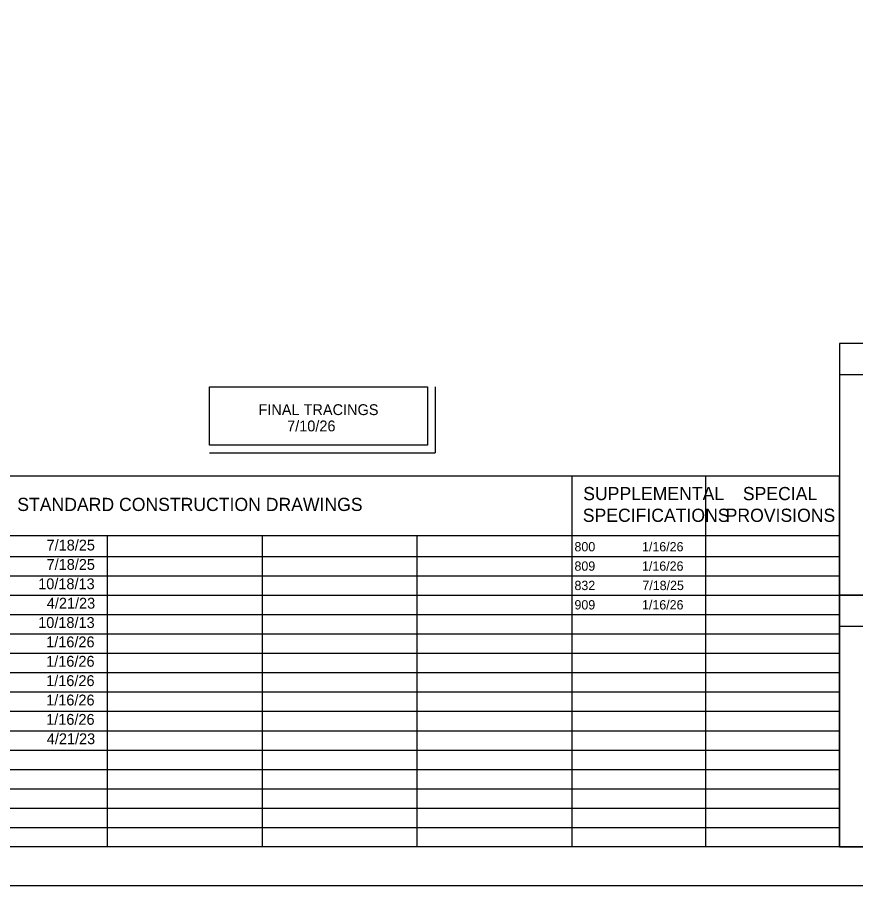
# Model space of a CAD drawing. Extents: x 0 to 34, y 0 to 22.
# Drawn here: x 12.99 to 23.81, y 0 to 11.21 of the extents above; entities that cross this region are included whole.
import ezdxf

# ---------------------------------------------------------------- set-up
doc = ezdxf.new("R2010")
doc.units = 0
for name, color, linetype in [('SH_Border', 7, 'Continuous'), ('SH_Cut_Line', 7, 'Continuous'), ('SH_Data', 7, 'Continuous'), ('SH_Text', 7, 'Continuous')]:
    doc.layers.add(name, color=color, linetype=linetype)

msp = doc.modelspace()

# ---------------------------------------------------------------- linework, layer by layer
at = {"layer": 'SH_Border'}
msp.add_lwpolyline([(1.5, 21.5), (33.5, 21.5), (33.5, 0.5), (1.5, 0.5)], close=True, dxfattribs=at)
at = {"layer": 'SH_Cut_Line'}
msp.add_lwpolyline([(0, 0), (34, 0), (34, 22), (0, 22)], close=True, dxfattribs=at)
at = {"layer": 'SH_Data'}
for p, q in [((23.6, 6.6), (26.4, 6.6)), ((10.15, 5.292), (23.6, 5.292)), ((20.15, 0.5), (20.15, 5.292)), ((21.875, 0.5), (21.875, 5.292)), ((23.6, 0.5), (23.6, 5.292)), ((10.15, 4.521), (23.6, 4.521)), ((14.15, 0.5), (14.15, 4.521)), ((16.15, 0.5), (16.15, 4.521)), ((18.15, 0.5), (18.15, 4.521)), ((10.15, 4.25), (23.6, 4.25)), ((10.15, 4), (23.6, 4)), ((10.15, 3.75), (23.6, 3.75)), ((10.15, 3.5), (23.6, 3.5)), ((23.6, 3.35), (26.4, 3.35)), ((10.15, 3.25), (23.6, 3.25)), ((10.15, 3), (23.6, 3)), ((10.15, 2.75), (23.6, 2.75)), ((10.15, 2.5), (23.6, 2.5)), ((10.15, 2.25), (23.6, 2.25)), ((10.15, 2), (23.6, 2)), ((10.15, 1.75), (23.6, 1.75)), ((10.15, 1.5), (23.6, 1.5)), ((10.15, 1.25), (23.6, 1.25)), ((10.15, 1), (23.6, 1)), ((10.15, 0.75), (23.6, 0.75))]:
    msp.add_line(p, q, dxfattribs=at)
for points in [[(26.4, 7), (23.6, 7), (23.6, 3.75), (26.4, 3.75)], [(26.4, 3.75), (23.6, 3.75), (23.6, 0.5), (26.4, 0.5)]]:
    msp.add_lwpolyline(points, close=True, dxfattribs=at)
at = {"layer": 'SH_Text'}
for p in [(18.381, 6.437), (15.469, 5.587)]:
    msp.add_line(p, (18.381, 5.587), dxfattribs=at)
msp.add_lwpolyline([(15.469, 6.437), (18.281, 6.437), (18.281, 5.687), (15.469, 5.687)], close=True, dxfattribs=at)

# ---------------------------------------------------------------- texts
for s, height, p in [('FINAL TRACINGS', 0.14, (16.1, 6.074)), ('7/10/26', 0.14, (16.47, 5.864)), ('SUPPLEMENTAL', 0.17, (20.293, 4.976)), ('SPECIAL', 0.17, (22.354, 4.976)), ('STANDARD CONSTRUCTION DRAWINGS', 0.17, (12.986, 4.836)), ('SPECIFICATIONS', 0.17, (20.287, 4.696)), ('PROVISIONS', 0.17, (22.132, 4.696)), ('7/18/25', 0.14, (13.364, 4.326)), ('800', 0.12, (20.18, 4.315)), ('1/16/26', 0.12, (21.052, 4.315)), ('7/18/25', 0.14, (13.364, 4.076)), ('809', 0.12, (20.18, 4.065)), ('1/16/26', 0.12, (21.052, 4.065)), ('10/18/13', 0.14, (13.256, 3.826)), ('832', 0.12, (20.18, 3.815)), ('7/18/25', 0.12, (21.057, 3.815)), ('4/21/23', 0.14, (13.367, 3.576)), ('909', 0.12, (20.18, 3.565)), ('1/16/26', 0.12, (21.052, 3.565)), ('10/18/13', 0.14, (13.256, 3.326)), ('1/16/26', 0.14, (13.359, 3.076)), ('1/16/26', 0.14, (13.359, 2.826)), ('1/16/26', 0.14, (13.359, 2.576)), ('1/16/26', 0.14, (13.359, 2.326)), ('1/16/26', 0.14, (13.359, 2.076)), ('4/21/23', 0.14, (13.367, 1.826))]:
    msp.add_text(s, height=height, dxfattribs=at).set_placement(p)

doc.saveas('drawing.dxf')
